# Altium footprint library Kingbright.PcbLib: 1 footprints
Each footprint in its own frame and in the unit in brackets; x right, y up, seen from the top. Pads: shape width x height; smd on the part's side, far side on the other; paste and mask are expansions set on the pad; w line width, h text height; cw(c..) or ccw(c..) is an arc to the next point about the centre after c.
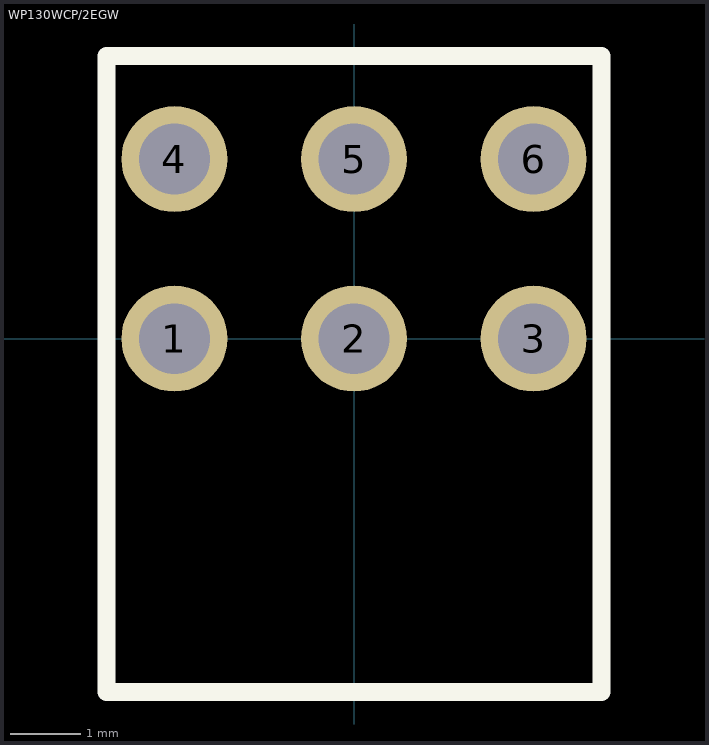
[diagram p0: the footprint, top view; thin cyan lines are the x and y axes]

## WP130WCP/2EGW [mm]
height 9.65
pads (6):
  round 1.5 hole 1: 1(-2.54,0) 2(0,0) 3(2.54,0) 4(-2.54,2.54) 5(0,2.54) 6(2.54,2.54)
Top Overlay:
  lines w0.254: -3.5,-5 -3.5,4 3.5,4 3.5,-5 -3.5,-5
3D body: height 9.02, standoff 0, extent -3.5,-5 3.5,4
